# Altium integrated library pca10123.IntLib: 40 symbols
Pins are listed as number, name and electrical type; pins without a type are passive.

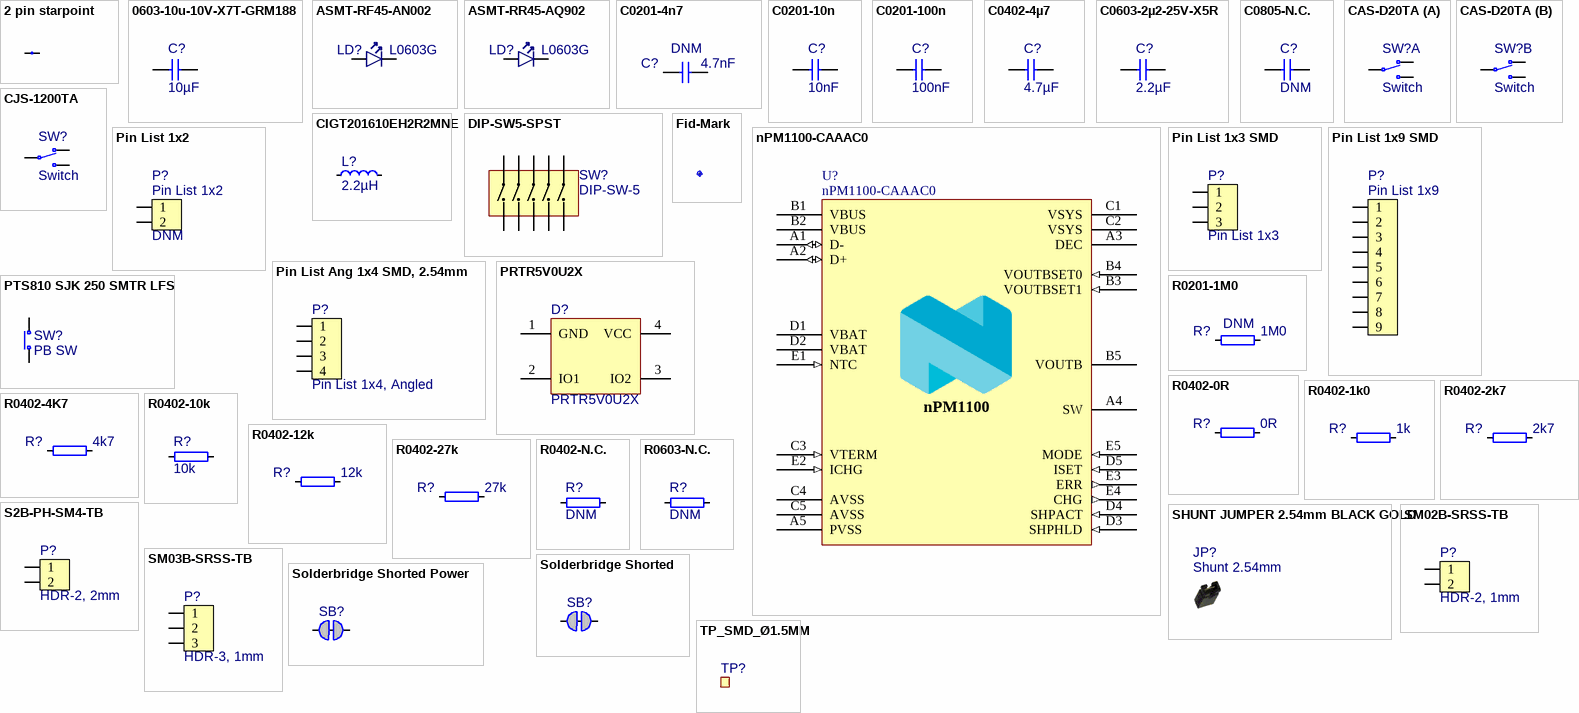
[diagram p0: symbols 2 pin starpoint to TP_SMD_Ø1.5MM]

## 2 pin starpoint
designator J?, comment N.A.  (value not drawn)  (net tie, no BOM)
Starpoint; Part Number: 2 pin starpoint; Pad Count: 2
footprint 2 PIN STARPOINT
pins: 1, 2

## 0603-10u-10V-X7T-GRM188
designator C?, comment 10µF
CAP CER 10UF 10V X7T 0603; Part Number: 0603-10u-10V-X7T-GRM188; Manufacturer: Murata; Manufacturer Part Number: GRM188D71A106MA73; Part number IPS: 00000004696; Note: 10VDC; Artikkelnr Noca: N.A.; Pad Count: 2
footprint CAPC1608X06L
pins: 1, 2

## ASMT-RF45-AN002
designator LD?, comment L0603G
LED, Yellow Green, 0603, Vf=2V, - 40 to +100°C; Part Number: ASMT-RF45-AN002; Manufacturer: Avago; Note: 28 mcd @ 20 mA; Artikkelnr Noca: N.A.; Pad Count: 2
footprint LED_0603_G
pins: 1 C, 2 A

## ASMT-RR45-AQ902
designator LD?, comment L0603G
LED, Red, 0603, Vf=2V, - 40 to +100°C; Part Number: ASMT-RR45-AQ902; Manufacturer: Avago; Note: 90 mcd @ 20 mA; Artikkelnr Noca: N.A.; Pad Count: 2
footprint LED_0603_R
pins: 1 C, 2 A

## C0201-4n7
designator C?, comment 4.7nF  Assembly: DNM
Chip Cap 0201 4.7nF 10% 10V X7R; Part Number: C0201-4n7; Manufacturer: N.A.; Part number IPS: 00000001243; Note: Chip Cap 1%; Pad Count: 2
footprint CAPC0603X03L_C
pins: 1, 2

## C0201-10n
designator C?, comment 10nF
Capacitor, X7R, ±10%; Part Number: C0201-10n; Manufacturer: N.A.; Part number IPS: 00000003480; Note: 10V; Pad Count: 2
footprint CAPC0603X03L_C
pins: 1, 2

## C0201-100n
designator C?, comment 100nF
Capacitor, X5R, ±10%; Part Number: C0201-100n; Manufacturer: N.A.; Part number IPS: 00000001248, 00000002505; Note: 16V; Pad Count: 2
footprint CAPC0603X03L_C
pins: 1, 2

## C0402-4µ7
designator C?, comment 4.7µF
Capacitor, X5R, ±20%; Part Number: C0402-4µ7; Manufacturer: N.A.; Part number IPS: 00000001251, 00000007165; Note: 10V; Artikkelnr Noca: 20039482; Pad Count: 2
footprint CAPC1005X04L
pins: 1, 2

## C0603-2µ2-25V-X5R
designator C?, comment 2.2µF
Capacitor, Ceramic, X5R, ±10%, 25V; Part Number: C0603-2µ2-25V-X5R; Manufacturer: Murata; Manufacturer Part Number: GRM188R61E225KA12D; Pad Count: 2; Artikkelnr Noca: N.A.
footprint CAPC1608X06L
pins: 1, 2

## C0805-N.C.
designator C?, comment DNM
Not mounted; Part Number: C0805-N.C.; Manufacturer: N.A.; Assembly: Not mounted; Note: Chip Cap; Pad Count: 2
footprint CAPC2012X11L_NC
pins: 1, 2

## CAS-D20TA
designator SW?, comment Switch
SMD slide Switch 2xSPDT; Part Number: CAS-D20TA; Manufacturer: Copal Electronics Inc; Note: N.A.; Pad Count: 6
footprint CAS-D20A
part A pins: 1 N.O, 2 COM, 3 N.C
part B pins: 4 N.O, 5 COM, 6 N.C

## CIGT201610EH2R2MNE
designator L?, comment 2.2µH
FIXED IND 2.2UH 2.5A 87MOHM SMD; Part Number: CIGT201610EH2R2MNE; Manufacturer: Samsung Electro-Mechanics; Pad Count: 2; Note: 2.2µH Unshielded Thin Film Inductor 2.5A 87mOhm Max 0806 (2016 Metric); Artikkelnr Noca: N.A.
footprint INDC2016X10N
pins: 1, 2

## CJS-1200TA
designator SW?, comment Switch
SMD slide Switch (ON-ON); Part Number: CJS-1200TA; Manufacturer: Copal Electronics Inc; Part number IPS: 00000009982; Note: N.A.; Artikkelnr Noca: 50019068; Pad Count: 3
footprint CJS-120xA
pins: 1 N.C, 2 COM, 3 N.O

## DIP-SW5-SPST
designator SW?, comment DIP-SW-5
SWITCH SLIDE DIP SPST 25MA 24V; Part Number: DIP-SW5-SPST; Manufacturer: Wurth Elektronik; Manufacturer Part Number: 416131160805; Note: N.A.; Pad Count: 10
footprint SOIC127P840X265-10N
pins: 1, 2, 3, 4, 5, 6, 7, 8, 9, 10

## Fid-Mark
designator Fid?, comment Fiducial mark  (value not drawn)
Part Number: Fid-Mark; Manufacturer: N.A.; Value: N.A.; Pad Count: 1
footprint Fiducial

## nPM1100-CAAAC0
designator U?
Li-Ion/Li-Polymer USB battery charger with a high efficiency buck regulator; Manufacturer: Nordic Semiconductor; Note: N.A.; Pad Count: 25
footprint BGA25C40P5X5_200X200X50
pins: A1 D- (io), A2 D+ (io), A3 DEC (power), A4 SW (power), A5 PVSS (power), B1 VBUS (power), B2 VBUS (power), B3 VOUTBSET1 (in), B4 VOUTBSET0 (in), B5 VOUTB (power), C1 VSYS (power), C2 VSYS (power), C3 VTERM (in), C4 AVSS (power), C5 AVSS (power), D1 VBAT (power), D2 VBAT (power), D3 SHPHLD (in), D4 SHPACT (in), D5 ISET (in), E1 NTC (in), E2 ICHG (in), E3 ERR (out), E4 CHG (out), E5 MODE (in)

## Pin List 1x2
designator P?  Assembly: DNM
Pin List 1x2, 2.54mm (100mil); Manufacturer: N.A.; Pad Count: 2; Artikkelnr Noca: 56019040
footprint LIST_1x2
pins: 1, 2

## Pin List 1x3 SMD
designator P?, comment Pin List 1x3
Pin List 1x3, 2.54mm (100mil), SMD; Part Number: Pin List 1x3 SMD; Manufacturer: W-CON; Manufacturer Part Number: 1125-1103S3M116CR02; Note: N.A.; Pad Count: 3
footprint LIST_1x3_SMD
pins: 1, 2, 3

## Pin List 1x9 SMD
designator P?, comment Pin List 1x9
Pin List 1x9, 2.54mm (100mil), SMD; Part Number: Pin List 1x9 SMD; Manufacturer: W-CON; Manufacturer Part Number: 1125-1109S0M116R2; Note: N.A.; Artikkelnr Noca: 55010024; Pad Count: 9
footprint LIST_1x9_SMD
pins: 1, 2, 3, 4, 5, 6, 7, 8, 9

## Pin List Ang 1x4 SMD, 2.54mm
designator P?, comment Pin List 1x4, Angled
Pin List 1x4, 2.54mm (100mil), Right Angled, SMD; Part Number: Pin List Ang 1x4 SMD, 2.54mm; Manufacturer: W-CON; Manufacturer Part Number: 1125B-1104S0Z135CR02; Part number IPS: 00000004780; Pad Count: 4; Note: N.A.
footprint LIST_ANG_1x4-SMD-2.54MM
pins: 1, 2, 3, 4

## PRTR5V0U2X
designator D?
Ultra low capacitance double rail-to-rail ESD protection diode; Manufacturer: NXP Semiconductors; Part number IPS: 00000009951; Note: N.A.; Artikkelnr Noca: 10069015; Pad Count: 4
footprint SOT190P230X110-4L
pins: 1 GND, 2 IO1, 3 IO2, 4 VCC

## PTS810 SJK 250 SMTR LFS
designator SW?, comment PB SW
Tactile Switch, SPNO, SMD, 260gf, 4.2x3.2x2.5mm; Part Number: PTS810 SJK 250 SMTR LFS; Manufacturer: C&K; Part number IPS: 00000001259; Note: N.A.; Pad Count: 4
footprint C&K_PTS810
pins: 1 N.O, 2 COM

## R0201-1M0
designator R?, comment 1M0  Assembly: DNM
Resistor, ±1%, 0.05W; Part Number: R0201-1M0; Manufacturer: N.A.; Part number IPS: 00000001418; Note: Chip Res 1%; Pad Count: 2
footprint RESC0603X03L_C
pins: 1, 2

## R0402-0R
designator R?, comment 0R
Resistor, ±5%, 0.063W; Part Number: R0402-0R; Manufacturer: N.A.; Part number IPS: 00000007128; Note: Chip Res 5%; Artikkelnr Noca: 27049000; Pad Count: 2
footprint RESC1005X04L
pins: 1, 2

## R0402-1k0
designator R?, comment 1k
Resistor, ±1%, 0.063W; Part Number: R0402-1k0; Manufacturer: N.A.; Part number IPS: 00000002218; Note: Chip Res 1%; Artikkelnr Noca: 27049073; Pad Count: 2
footprint RESC1005X04L
pins: 1, 2

## R0402-2k7
designator R?, comment 2k7
Resistor, ±1%, 0.063W; Part Number: R0402-2k7; Manufacturer: N.A.; Note: Chip Res 1%; Artikkelnr Noca: 27049083; Pad Count: 2
footprint RESC1005X04L
pins: 1, 2

## R0402-4K7
designator R?, comment 4k7
Resistor, ±1%, 0.063W; Part Number: R0402-4k7; Manufacturer: N.A.; Part number IPS: 00000003433; Note: Chip Res 1%; Artikkelnr Noca: 27049089; Pad Count: 2
footprint RESC1005X04L
pins: 1, 2

## R0402-10k
designator R?, comment 10k
Resistor, ±1%, 0.063W; Part Number: R0402-10k; Manufacturer: N.A.; Part number IPS: 00000002093; Note: Chip Res 1%; Artikkelnr Noca: 27049097; Pad Count: 2
footprint RESC1005X04L
pins: 1, 2

## R0402-12k
designator R?, comment 12k
Resistor, ±1%, 0.063W; Part Number: R0402-12k; Manufacturer: N.A.; Note: Chip Res 1%; Artikkelnr Noca: 27049099; Pad Count: 2
footprint RESC1005X04L
pins: 1, 2

## R0402-27k
designator R?, comment 27k
Resistor, ±1%, 0.063W; Part Number: R0402-27k; Manufacturer: N.A.; Part number IPS: 00000004188; Note: Chip Res 1%; Artikkelnr Noca: 27049107; Pad Count: 2
footprint RESC1005X04L
pins: 1, 2

## R0402-N.C.
designator R?, comment DNM
Not mounted; Part Number: R0402-N.C.; Manufacturer: N.A.; Assembly: Not mounted; Note: Chip Res; Pad Count: 2
footprint RESC1005X04L_NC
pins: 1, 2

## R0603-N.C.
designator R?, comment DNM
Not mounted; Part Number: R0603-N.C.; Manufacturer: N.A.; Assembly: Not mounted; Note: Chip Res; Pad Count: 2
footprint RESC1608X06L_NC
pins: 1, 2

## S2B-PH-SM4-TB
designator P?, comment HDR-2, 2mm
2.0mm pitch connector side entry SMD; Part Number: S2B-PH-SM4-TB; Manufacturer: JST Sales America Inc.; Manufacturer Part Number: S2B-PH-SM4-TB(LF)(SN); Note: JST, Header; Artikkelnr Noca: N.A.; Pad Count: 2
footprint S2B-PH-SM4-TB
pins: 1, 2

## SHUNT JUMPER 2.54mm BLACK GOLD
designator JP?, comment Shunt 2.54mm
SHUNT JUMPER .1" BLACK GOLD; Part Number: SHUNT JUMPER 2.54mm BLACK GOLD; Manufacturer: 3M; Manufacturer Part Number: 969102-0000-DA; Part number IPS: N.A.; Note: SHUNT JUMPER .1" BLACK GOLD, h=6.00mm, w=5.00mm; Artikkelnr Noca: 56099001; Pad Count: 2
footprint Shunt_2.54mm

## SM02B-SRSS-TB
designator P?, comment HDR-2, 1mm
1.0mm pitch connector side entry SMD; Part Number: SM02B-SRSS-TB; Manufacturer: JST Sales America Inc.; Manufacturer Part Number: SM02B-SRSS-TB(LF)(SN); Part number IPS: 00000007791; Part number Norautron: N.A.; Note: JST, Header; Artikkelnr Noca: 55010030; Pad Count: 2
footprint SM02B-SRSS-TB
pins: 1, 2

## SM03B-SRSS-TB
designator P?, comment HDR-3, 1mm
1.0mm pitch connector side entry SMD; Part Number: SM03B-SRSS-TB; Manufacturer: JST Sales America Inc.; Manufacturer Part Number: SM03B-SRSS-TB(LF)(SN); Part number IPS: 00000001785; Note: JST, Header; Artikkelnr Noca: N.A.; Pad Count: 3
footprint SM03B-SRSS-TB
pins: 1, 2, 3

## Solderbridge Shorted
designator SB?, comment Solderbridge  (value not drawn)  (net tie, no BOM)
Shorted Solderbridge; Part Number: Solderbridge Shorted; Manufacturer: N.A.; Pad Count: 2
footprint Solderbridge_Shorted
pins: 1 0, 2 1

## Solderbridge Shorted Power
designator SB?, comment Solderbridge  (value not drawn)  (net tie, no BOM)
Shorted Solderbridge Power; Part Number: Solderbridge Shorted Power; Manufacturer: N.A.; Pad Count: 2
footprint Solderbridge_Shorted_Power
pins: 1 0, 2 1

## TP_SMD_Ø1.5MM
designator TP?, comment Ø1.5mm,SMD  (value not drawn)  (no BOM)
1.5mm circular SMD testpad; Part Number: TP_SMD_Ø1.5MM; Manufacturer: Nordic Semiconductor; Manufacturer Part Number: N.A.; Pad Count: 1
footprint TP_SMD_D1.5mm
pins: 1

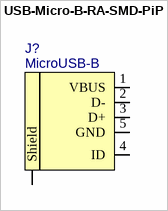
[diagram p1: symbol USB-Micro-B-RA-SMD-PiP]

## USB-Micro-B-RA-SMD-PiP
designator J?, comment MicroUSB-B
MicroUSB-B-SMT; Part Number: USB-Micro-B-RA-SMD-PiP; Manufacturer: Allen Creations Corp.; Manufacturer Part Number: AJU55-BS2111-L; Part number IPS: 00000007790; Note: N.A.; Artikkelnr Noca: 55029020; Pad Count: 5
footprint USB-Micro-B-RA-SMD-PiP
pins: 1 VBUS (power), 2 D-, 3 D+, 4 ID, 5 GND (power), 6 Shield (power)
